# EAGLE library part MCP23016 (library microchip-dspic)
16-Bit I/O Expander with I2C Interface
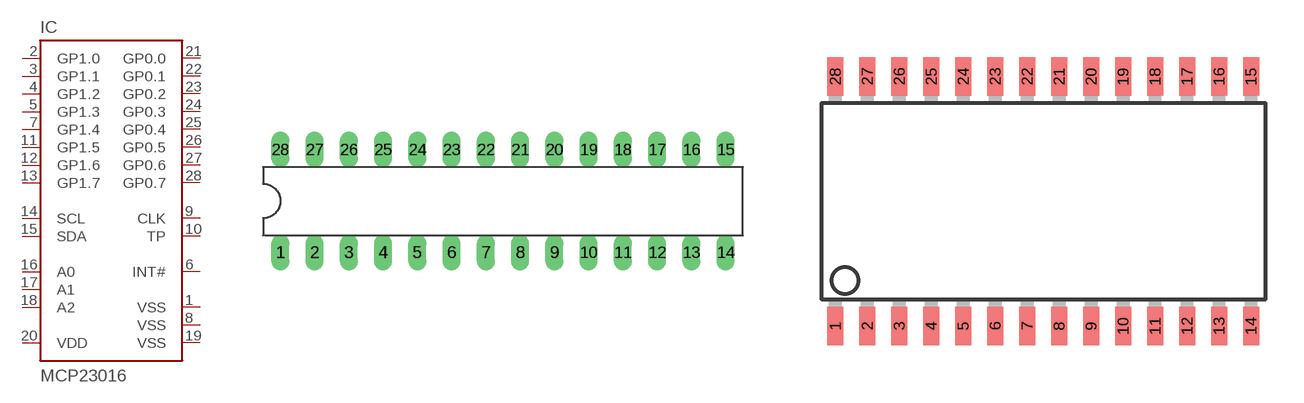
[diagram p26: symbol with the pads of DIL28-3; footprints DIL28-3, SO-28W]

Designator prefix IC

## MCP23016P  [DIL28-3]
1  VSS  pwr
2  GP1.0
3  GP1.1
4  GP1.2
5  GP1.3
6  INT#  out
7  GP1.4
8  VSS  pwr
9  CLK  in
10  TP  out
11  GP1.5
12  GP1.6
13  GP1.7
14  SCL  in
15  SDA
16  A0  in
17  A1  in
18  A2  in
19  VSS  pwr
20  VDD  pwr
21  GP0.0
22  GP0.1
23  GP0.2
24  GP0.3
25  GP0.4
26  GP0.5
27  GP0.6
28  GP0.7

## MCP23016SO  [SO-28W]
Pads as for DIL28-3

## MCP23016SS  [SSOP28]
Pads as for DIL28-3

## MCP23016ML  [QFN-S28-6X6]
1  GP1.2
2  GP1.3
3  INT#  out
4  GP1.4
5  VSS  pwr
6  CLK  in
7  TP  out
8  GP1.5
9  GP1.6
10  GP1.7
11  SCL  in
12  SDA
13  A0  in
14  A1  in
15  A2  in
16  VSS  pwr
17  VDD  pwr
18  GP0.0
19  GP0.1
20  GP0.2
21  GP0.3
22  GP0.4
23  GP0.5
24  GP0.6
25  GP0.7
26  VSS  pwr
27  GP1.0
28  GP1.1

## Footprint DIL28-3 (pad centres in mm)
Dual In Line package type P
drill 0.813 long: 1 -16.51,-3.81; 2 -13.97,-3.81; 3 -11.43,-3.81; 4 -8.89,-3.81; 5 -6.35,-3.81; 6 -3.81,-3.81; 7 -1.27,-3.81; 8 1.27,-3.81; 9 3.81,-3.81; 10 6.35,-3.81; 11 8.89,-3.81; 12 11.43,-3.81; 13 13.97,-3.81; 14 16.51,-3.81; 15 16.51,3.81; 16 13.97,3.81; 17 11.43,3.81; 18 8.89,3.81; 19 6.35,3.81; 20 3.81,3.81; 21 1.27,3.81; 22 -1.27,3.81; 23 -3.81,3.81; 24 -6.35,3.81; 25 -8.89,3.81; 26 -11.43,3.81; 27 -13.97,3.81; 28 -16.51,3.81

## Footprint SO-28W (pad centres in mm)
Small Outline Wide Plastic Gull Wing 300-mil body, package type SO
smd 0.635 x 1.524: 1 -7.62,-4.953; 2 -6.35,-4.953; 3 -5.08,-4.953; 4 -3.81,-4.953; 5 -2.54,-4.953; 6 -1.27,-4.953; 7 0,-4.953; 8 1.27,-4.953; 9 2.54,-4.953; 10 3.81,-4.953; 11 5.08,-4.953; 12 6.35,-4.953; 13 7.62,-4.953; 14 8.89,-4.953; 15 8.89,4.953; 16 7.62,4.953; 17 6.35,4.953; 18 5.08,4.953; 19 3.81,4.953; 20 2.54,4.953; 21 1.27,4.953; 22 0,4.953; 23 -1.27,4.953; 24 -2.54,4.953; 25 -3.81,4.953; 26 -5.08,4.953; 27 -6.35,4.953; 28 -7.62,4.953

## Footprint SSOP28 (pad centres in mm)
Shrink Small Outline Package package type SS
smd 0.4 x 1.5: 1 -4.225,-3.625; 2 -3.575,-3.625; 3 -2.925,-3.625; 4 -2.275,-3.625; 5 -1.625,-3.625; 6 -0.975,-3.625; 7 -0.325,-3.625; 8 0.325,-3.625; 9 0.975,-3.625; 10 1.625,-3.625; 11 2.275,-3.625; 12 2.925,-3.625; 13 3.575,-3.625; 14 4.225,-3.625; 15 4.225,3.625; 16 3.575,3.625; 17 2.925,3.625; 18 2.275,3.625; 19 1.625,3.625; 20 0.975,3.625; 21 0.325,3.625; 22 -0.325,3.625; 23 -0.975,3.625; 24 -1.625,3.625; 25 -2.275,3.625; 26 -2.925,3.625; 27 -3.575,3.625; 28 -4.225,3.625

## Footprint QFN-S28-6X6 (pad centres in mm)
Quad Flat No Lead
smd 0.6 x 0.4: 1 2.75,-1.95; 2 2.75,-1.3; 3 2.75,-0.65; 4 2.75,0; 5 2.75,0.65; 6 2.75,1.3; 7 2.75,1.95; 15 -2.75,1.95; 16 -2.75,1.3; 17 -2.75,0.65; 18 -2.75,0; 19 -2.75,-0.65; 20 -2.75,-1.3; 21 -2.75,-1.95
smd 0.4 x 0.6: 8 1.95,2.75; 9 1.3,2.75; 10 0.65,2.75; 11 0,2.75; 12 -0.65,2.75; 13 -1.3,2.75; 14 -1.95,2.75; 22 -1.95,-2.75; 23 -1.3,-2.75; 24 -0.65,-2.75; 25 0,-2.75; 26 0.65,-2.75; 27 1.3,-2.75; 28 1.95,-2.75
